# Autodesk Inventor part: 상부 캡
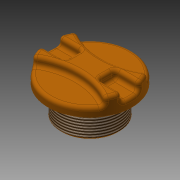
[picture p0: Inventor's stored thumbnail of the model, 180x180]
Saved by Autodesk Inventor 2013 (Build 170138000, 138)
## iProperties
Created: 2016-09
Part Number: 상부 캡
Material: 고무
Document SubType Name: Modeling
Designer: mduedu
Density: 1.493 g/cm^3
Mass: 36.0632 g
Surface Area: 76.9413 cm^2
Volume: 24.1549 cm^3
Author: mduedu
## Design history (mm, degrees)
sketch "스케치1"
  geometry: C1 r 25 at (0, 0); 1 further point
  constraints: 1 centre point, 1 coincident
  dimensions: "d0" = 50 diameter of C1
extrude "돌출1" new body sketch "스케치1" distance "d1" = 10; taper "d2" = 0 deg
sketch "스케치2" dims "d4" = 80
  geometry: C1 r 25 at (0, 0) reference; 3 further points
  constraints: 3 vertical alignment, 2 other
  dimensions: "d3" = 7 distance of point (0, 7) point (0, 0)
extrude "돌출2" cut sketch "스케치2" distance "d5" = 5; taper "d6" = 0 deg
sketch "스케치3"
  geometry: L1 (-25, 0)-(0, 0); L2 (-24.495, 5)-(-10, 5); L3 (-10, 5)-(-10, -5); L4 (-10, -5)-(-24.495, -5); A1 r 25 centre (0, 0) between (-21.276, 13.128) and (-21.276, -13.128) reference; A2 r 25 centre (0, 0) between (-24.495, 5) and (-24.495, -5); 1 further point
  constraints: 8 end point, 5 point on circle, 2 horizontal, 1 centre point, 1 coincident, 1 parallel, 1 perpendicular, 1 symmetric about line
  dimensions: "d7" = 10 distance from line of L3 point (0, 0); "d8" = 10 distance of L2.end L3.end
extrude "돌출3" cut sketch "스케치3" distance "d9" = 5; taper "d10" = 0 deg
fillet "모깎기1" dims "d11" = 2
fillet "모깎기2" dims "d12" = 2
fillet "모깎기3" dims "d13" = 2
sketch "스케치4"
  geometry: C1 r 17.5 at (0, 0); 1 further point
  constraints: 1 centre point, 1 coincident
  dimensions: "d14" = 35 diameter of C1
extrude "돌출4" join sketch "스케치4" distance "d15" = 17; taper "d16" = 0 deg
sketch "스케치5"
  geometry: C1 r 12.5 at (0, 0); 1 further point
  constraints: 1 centre point, 1 coincident
  dimensions: "d17" = 25 diameter of C1
extrude "돌출5" cut sketch "스케치5" distance "d18" = 10; taper "d19" = 0 deg
fillet "모깎기4" dims "d20" = 3
feature "스레드1" dims "d21" = 10, "d22" = 0
chamfer "모따기1" distance "d23" = 1; stored, may be unused: second distance "d24" = 2, angle "d25" = 45 deg
node "솔리드1"
mirror "대칭1"
mirror "대칭2"
node "투영된 루프1"
